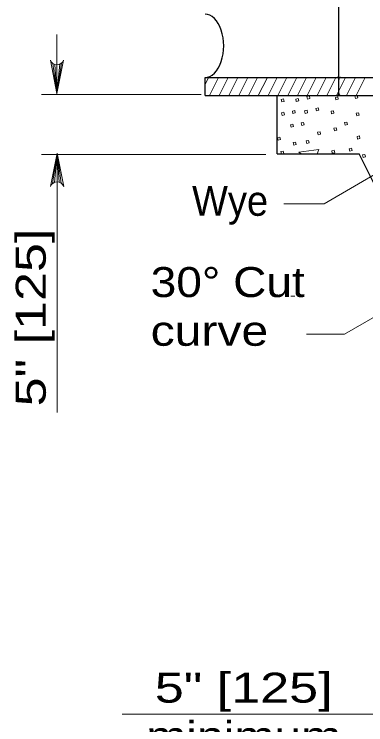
# Model space of a CAD drawing. Extents: x 750.7 to 784.7, y 860.1 to 882.1.
# Drawn here: x 758.48 to 760.358, y 872.527 to 876.32 of the extents above; entities that cross this region are included whole.
import ezdxf
from ezdxf.enums import TextEntityAlignment as Align

# ---------------------------------------------------------------- set-up
doc = ezdxf.new("R2010")
doc.units = 0
doc.header["$LTSCALE"] = 0.064
doc.layers.add('1', color=7, linetype='Continuous', lineweight=13)

msp = doc.modelspace()

# ---------------------------------------------------------------- linework, layer by layer
at = {"layer": '1', "lineweight": 25}
for p, q in [((760.21367, 875.89692), (760.21358, 876.83908)), ((759.49933, 875.88608), (759.49933, 875.98233)), ((759.49933, 875.98233), (760.20417, 875.98233)), ((760.22308, 875.98233), (760.50133, 875.98233)), ((759.49933, 875.88608), (760.453, 875.88608)), ((759.885, 875.57417), (759.885, 875.88767)), ((759.885, 875.57417), (760.3215, 875.57417)), ((760.59067, 875.03808), (760.3215, 875.57417))]:
    msp.add_line(p, q, dxfattribs=at)
at = {"layer": '1'}
for p, q in [((758.7085, 875.8915), (758.7085, 876.21092)), ((758.68608, 876.05708), (758.7085, 875.89675)), ((758.69717, 876.05167), (758.7085, 875.89675)), ((758.73333, 876.05892), (758.7085, 875.89675)), ((758.72292, 876.05283), (758.7085, 875.89675)), ((758.7085, 876.05), (758.7085, 875.89675)), ((759.49933, 875.94467), (759.51817, 875.98233)), ((759.52233, 875.88608), (759.57042, 875.98233)), ((759.57467, 875.88608), (759.62275, 875.98233)), ((759.62692, 875.88608), (759.675, 875.98233)), ((759.67917, 875.88608), (759.72733, 875.98233)), ((759.7315, 875.88608), (759.77958, 875.98233)), ((759.78375, 875.88608), (759.83192, 875.98233)), ((759.83608, 875.88608), (759.88417, 875.98233)), ((759.88833, 875.88608), (759.93642, 875.98233)), ((759.94067, 875.88608), (759.98875, 875.98233)), ((759.99292, 875.88608), (760.041, 875.98233)), ((760.04525, 875.88608), (760.09333, 875.98233)), ((760.0975, 875.88608), (760.14558, 875.98233)), ((760.14975, 875.88608), (760.19792, 875.98233)), ((760.20208, 875.88608), (760.25017, 875.98233)), ((760.25433, 875.88608), (760.3025, 875.98233)), ((760.30667, 875.88608), (760.35475, 875.98233)), ((759.47933, 875.8915), (758.62633, 875.8915)), ((760.09833, 875.57417), (760.10633, 875.59825)), ((759.82392, 875.57092), (758.62633, 875.57092)), ((758.68425, 875.41575), (758.70908, 875.578)), ((758.69467, 875.42192), (758.70908, 875.578)), ((758.70908, 875.42475), (758.70908, 875.578)), ((758.72042, 875.42308), (758.70908, 875.578)), ((758.7315, 875.41767), (758.70908, 875.578)), ((758.70908, 874.19383), (758.70908, 875.57092)), ((759.9565, 874.8155), (759.97792, 874.8155)), ((760.59067, 872.58275), (759.05642, 872.58275))]:
    msp.add_line(p, q, dxfattribs=at)
for points in [[(758.74392, 876.07383), (758.7085, 875.89675), (758.67308, 876.07383)], [(760.31158, 875.8865), (760.31467, 875.87375), (760.30208, 875.87075), (760.29892, 875.884), (760.30933, 875.8865)], [(759.90675, 875.57417), (759.90383, 875.58625), (759.91642, 875.58925)], [(759.91642, 875.58925), (759.91958, 875.57608), (759.91175, 875.57417)], [(760.10633, 875.59825), (760.00092, 875.58417), (760.01208, 875.57417)], [(758.67367, 875.40092), (758.70908, 875.578), (758.7445, 875.40092)], [(760.59917, 875.57717), (760.13458, 875.30725), (759.92033, 875.30725)], [(760.87825, 874.97617), (760.24342, 874.6115), (760.0405, 874.6115)]]:
    msp.add_lwpolyline(points, dxfattribs=at)
for points in [[(759.91892, 875.86775), (759.92208, 875.8545), (759.9095, 875.8515), (759.90633, 875.86475)], [(759.996, 875.87008), (759.99925, 875.85683), (759.98667, 875.85383), (759.9835, 875.86708)], [(760.05617, 875.88342), (760.05933, 875.87017), (760.04675, 875.86717), (760.04358, 875.88042)], [(760.20767, 875.87883), (760.21083, 875.86558), (760.19825, 875.86258), (760.19508, 875.87583)], [(760.10383, 875.82017), (760.107, 875.80692), (760.0945, 875.80392), (760.09125, 875.81717)], [(759.92042, 875.79617), (759.92367, 875.78292), (759.91108, 875.77992), (759.90792, 875.79317)], [(759.97792, 875.80583), (759.98117, 875.79258), (759.96858, 875.78958), (759.96542, 875.80283)], [(760.04375, 875.80675), (760.04692, 875.7935), (760.03433, 875.7905), (760.03117, 875.80375)], [(760.18458, 875.80475), (760.18783, 875.7915), (760.17525, 875.7885), (760.17208, 875.80175)], [(760.31867, 875.794), (760.32183, 875.78075), (760.30925, 875.77775), (760.30608, 875.791)], [(760.02567, 875.74258), (760.02883, 875.72933), (760.01625, 875.72633), (760.01308, 875.73958)], [(760.25717, 875.744), (760.26042, 875.73075), (760.24783, 875.72775), (760.24458, 875.741)], [(759.96817, 875.73292), (759.97133, 875.71967), (759.95875, 875.71667), (759.95558, 875.72992)], [(760.19967, 875.71375), (760.20283, 875.7005), (760.19033, 875.6975), (760.18708, 875.71075)], [(759.89858, 875.66367), (759.90175, 875.65042), (759.88917, 875.64742), (759.886, 875.66067)], [(760.11317, 875.69233), (760.11633, 875.67908), (760.10375, 875.67608), (760.10058, 875.68933)], [(760.3235, 875.66992), (760.32667, 875.65667), (760.31408, 875.65367), (760.31092, 875.66692)], [(759.98258, 875.63733), (759.98575, 875.62408), (759.97317, 875.62108), (759.97, 875.63433)], [(760.05167, 875.64633), (760.05492, 875.63308), (760.04233, 875.63017), (760.03917, 875.64333)], [(760.18825, 875.59375), (760.1915, 875.5805), (760.17892, 875.5775), (760.17575, 875.59075)], [(760.282, 875.60492), (760.28517, 875.59167), (760.27258, 875.58867), (760.26942, 875.60192)], [(760.35317, 875.57158), (760.35642, 875.55833), (760.34383, 875.55533), (760.34067, 875.56858)]]:
    msp.add_lwpolyline(points, close=True, dxfattribs=at)
for centre, start, end in [((758.70849, 876.08813), 202.08782, 337.91395), ((758.70911, 875.38661), 22.08782, 157.91395)]:
    msp.add_arc(centre, 0.03822, start, end, dxfattribs=at)
at = {"layer": '1', "lineweight": 25}
for centre, major_axis, ratio, start_param, end_param in [((759.49932, 876.15107), (0, 0.16876), 0.588476, 3.1415978, 6.2831905), ((760.20418, 875.97146), (0, 0.01086), 0.869565, 4.7124054, 6.2831838), ((760.22307, 875.97146), (0, 0.01086), 0.869565, 0.000002, 1.5708127), ((760.20418, 875.89695), (0, 0.01086), 0.869565, 3.1415919, 4.7124054), ((760.22307, 875.89695), (0, -0.01086), 0.869565, 4.712406, 6.2831852)]:
    msp.add_ellipse(centre, major_axis=major_axis, ratio=ratio, start_param=start_param, end_param=end_param, dxfattribs=at)

# ---------------------------------------------------------------- texts
at = {"layer": '1'}
for s, width, p in [('Wye', 0.95, (759.42958, 875.24367)), ('30° Cut', 1.15, (759.20875, 874.80992)), ('curve', 1.2, (759.20875, 874.54992))]:
    msp.add_text(s, height=0.16, dxfattribs=dict(at, width=width)).set_placement(p)
at = {"layer": '1', "width": 1.3}
msp.add_text('5" [125]', height=0.16, rotation=90, dxfattribs=at).set_placement((758.6485, 874.22633))
at = {"layer": '1'}
for s, width, p in [('5" [125]', 1.3, (759.70558, 872.64492)), ('minimum', 1.2, (759.70558, 872.38492))]:
    msp.add_text(s, height=0.16, dxfattribs=dict(at, width=width)).set_placement(p, align=Align.CENTER)

doc.saveas('drawing.dxf')
